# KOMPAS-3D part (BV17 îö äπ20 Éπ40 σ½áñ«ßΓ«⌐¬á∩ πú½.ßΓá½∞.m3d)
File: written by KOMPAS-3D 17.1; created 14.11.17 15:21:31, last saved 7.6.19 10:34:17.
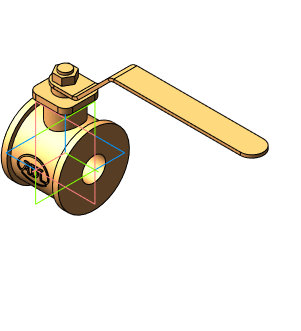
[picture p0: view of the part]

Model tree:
1. Операция без истории:1  (labels: Сталь 20  ГОСТ 1050-2013)

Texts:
  Линейный размер с обрывом
  Толщина листового тела
  Глубина освобождения сгиба
  Ширина освобождения сгиба
  BV17 МФ Ду15 Ру40 хладостойкая угл.сталь
  BV17 МФ Ду20 Ру40 хладостойкая угл.сталь
  BV17 МФ Ду25 Ру40 хладостойкая угл.сталь
  BV17 МФ Ду32 Ру40 хладостойкая угл.сталь
  BV17 МФ Ду40 Ру40 хладостойкая угл.сталь
  BV17 МФ Ду50 Ру40 хладостойкая угл.сталь
  BV17 МФ Ду65 Ру40 хладостойкая угл.сталь
  BV17 МФ Ду80 Ру40 хладостойкая угл.сталь
  BV17 МФ Ду100 Ру40 хладостойкая угл.сталь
